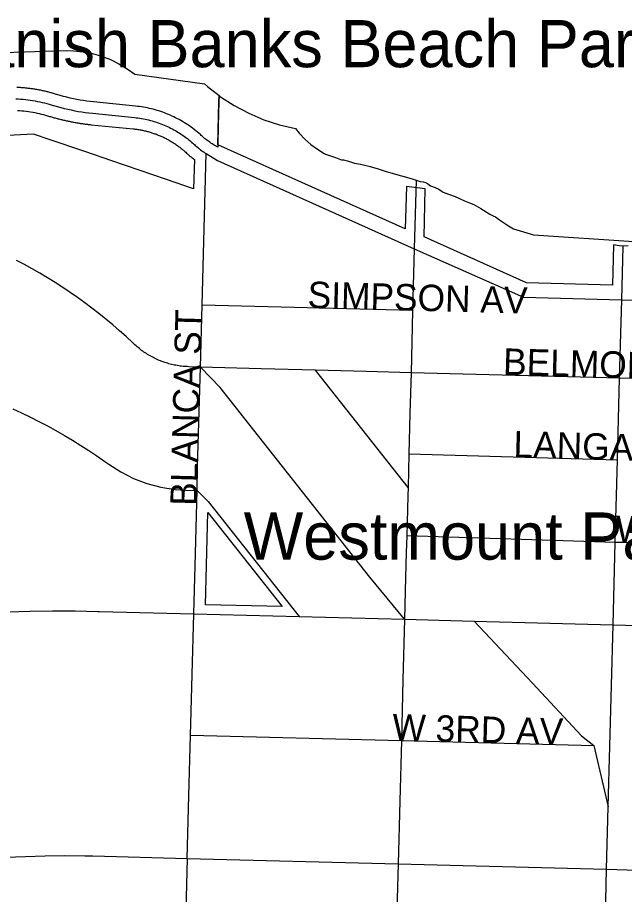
# Model space of a CAD drawing. Extents: x 482780 to 486928, y 5455974 to 5459836.
# Drawn here: x 484178 to 484821, y 5457356 to 5458285 of the extents above; entities that cross this region are included whole.
import ezdxf

# ---------------------------------------------------------------- set-up
doc = ezdxf.new("R2010")
doc.units = 0
for name, color, linetype in [('ParkLabels', 7, 'Continuous'), ('Parks', 7, 'Continuous'), ('StreetNames', 7, 'Continuous'), ('Streets', 7, 'Continuous')]:
    doc.layers.add(name, color=color, linetype=linetype)

msp = doc.modelspace()

# ---------------------------------------------------------------- linework, layer by layer
at = {"layer": 'Parks'}
for points in [[(484129.18, 5458247.37), (484229.39, 5458250.29), (484237.17, 5458250.08), (484247.16, 5458249.02), (484257.03, 5458247.1), (484266.69, 5458244.32), (484276.07, 5458240.71), (484285.1, 5458236.3), (484293.71, 5458231.12), (484301.84, 5458225.21), (484375.68, 5458215.19), (484379.16, 5458212.14), (484391.29, 5458202.66), (484391.11, 5458196.1), (484390.44, 5458170.7), (484389.91, 5458150.4), (484389.87, 5458147.97), (484388.64, 5458148.63), (484387.41, 5458149.32), (484386.21, 5458150.02), (484385.01, 5458150.74), (484383.83, 5458151.49), (484382.66, 5458152.25), (484381.5, 5458153.04), (484380.36, 5458153.85), (484379.23, 5458154.67), (484378.12, 5458155.52), (484377.02, 5458156.38), (484375.93, 5458157.26), (484374.86, 5458158.17), (484373.81, 5458159.09), (484373.25, 5458159.59), (484372.31, 5458160.44), (484371.5, 5458161.18), (484369.9, 5458162.58), (484368.28, 5458163.95), (484366.64, 5458165.29), (484364.97, 5458166.6), (484363.28, 5458167.89), (484361.57, 5458169.14), (484359.83, 5458170.37), (484358.08, 5458171.56), (484356.3, 5458172.72), (484354.5, 5458173.86), (484352.69, 5458174.96), (484350.85, 5458176.02), (484349, 5458177.06), (484347.13, 5458178.06), (484345.24, 5458179.04), (484343.34, 5458179.97), (484341.42, 5458180.88), (484339.48, 5458181.75), (484337.53, 5458182.59), (484335.56, 5458183.39), (484333.59, 5458184.16), (484331.59, 5458184.89), (484329.59, 5458185.59), (484327.57, 5458186.26), (484325.55, 5458186.88), (484323.51, 5458187.48), (484321.46, 5458188.04), (484319.4, 5458188.56), (484317.33, 5458189.04), (484315.26, 5458189.49), (484313.17, 5458189.91), (484311.09, 5458190.28), (484308.99, 5458190.62), (484306.89, 5458190.93), (484304.78, 5458191.19), (484302.67, 5458191.42), (484258.2, 5458195.89), (484254.62, 5458196.28), (484251.05, 5458196.74), (484247.49, 5458197.27), (484243.94, 5458197.85), (484240.4, 5458198.5), (484236.87, 5458199.21), (484233.36, 5458199.97), (484229.86, 5458200.81), (484226.37, 5458201.7), (484222.9, 5458202.65), (484219.44, 5458203.66), (484218.75, 5458203.87), (484216.71, 5458204.49), (484215.74, 5458204.78), (484214.77, 5458205.07), (484213.8, 5458205.34), (484212.83, 5458205.62), (484211.85, 5458205.88), (484210.88, 5458206.14), (484209.9, 5458206.4), (484208.92, 5458206.64), (484207.94, 5458206.89), (484206.95, 5458207.12), (484205.97, 5458207.35), (484204.98, 5458207.57), (484203.99, 5458207.79), (484203.01, 5458208), (484202.02, 5458208.2), (484201.02, 5458208.4), (484200.03, 5458208.59), (484199.04, 5458208.77), (484198.04, 5458208.95), (484197.05, 5458209.12), (484196.05, 5458209.29), (484195.05, 5458209.45), (484194.05, 5458209.6), (484193.05, 5458209.75), (484192.05, 5458209.89), (484191.05, 5458210.02), (484190.05, 5458210.15), (484189.04, 5458210.27), (484188.04, 5458210.38), (484187.04, 5458210.49), (484186.03, 5458210.59), (484185.02, 5458210.69), (484184.02, 5458210.78), (484183.01, 5458210.86), (484182, 5458210.94), (484180.99, 5458211.01), (484179.98, 5458211.07), (484179.97, 5458211.07), (484178.97, 5458211.13), (484177.97, 5458211.18), (484176.96, 5458211.22)], [(484824.88, 5458043.24), (484819.72, 5458042.76), (484815.42, 5458043.24), (484809.47, 5458044.25), (484808.32, 5458001.61), (484717.07, 5458004.05), (484608.51, 5458052.7), (484609.84, 5458103.83), (484589.8, 5458106.23), (484588.61, 5458061.2), (484389.91, 5458150.4), (484391.11, 5458196.1), (484391.29, 5458202.66), (484392.85, 5458201.44), (484407.42, 5458191.96), (484422.77, 5458183.78), (484438.77, 5458176.98), (484455.29, 5458171.59), (484472.23, 5458167.67), (484476.33, 5458162.62), (484482.19, 5458156.45), (484488.57, 5458150.8), (484495.42, 5458145.73), (484502.68, 5458141.27), (484504.24, 5458140.54), (484514.71, 5458136.8), (484518.07, 5458135.5), (484519.86, 5458134.85), (484521.01, 5458134.64), (484523.01, 5458134.4), (484528.31, 5458132.97), (484534.86, 5458131.1), (484541.18, 5458129.87), (484545.61, 5458128.95), (484551.31, 5458127.41), (484559.81, 5458124.9), (484568.36, 5458122.19), (484574.71, 5458120.2), (484580.81, 5458118.52), (484590.06, 5458116.05), (484596.89, 5458113.94), (484604.26, 5458111.65), (484607.48, 5458111.07), (484610.01, 5458110.55), (484612.24, 5458109.26), (484615.51, 5458107.05), (484620.24, 5458105.06), (484624.16, 5458103.35), (484626.66, 5458101.73), (484628.91, 5458100.3), (484634.32, 5458098.22), (484641.46, 5458095.7), (484646.73, 5458093.16), (484651.36, 5458090.95), (484656.65, 5458088.92), (484661.31, 5458087.1), (484668.56, 5458082.88), (484678.41, 5458076.8), (484681.79, 5458075.1), (484684.11, 5458073.9), (484688.6, 5458070.99), (484697.92, 5458064.4), (484699.62, 5458063.37), (484703.15, 5458061.47), (484724.68, 5458054.79), (484831.03, 5458048.04)], [(484177.54, 5458186.83), (484179.87, 5458186.69), (484182.19, 5458186.51), (484184.51, 5458186.29), (484186.83, 5458186.02), (484189.14, 5458185.72), (484191.44, 5458185.38), (484193.74, 5458184.99), (484196.03, 5458184.57), (484198.32, 5458184.11), (484200.6, 5458183.6), (484202.86, 5458183.06), (484205.12, 5458182.48), (484207.37, 5458181.86), (484209.6, 5458181.2), (484211.66, 5458180.59), (484212.64, 5458180.29), (484213.62, 5458180), (484214.6, 5458179.72), (484215.59, 5458179.43), (484216.57, 5458179.15), (484217.56, 5458178.88), (484218.55, 5458178.61), (484219.54, 5458178.35), (484220.53, 5458178.08), (484221.52, 5458177.83), (484222.51, 5458177.58), (484223.5, 5458177.33), (484224.5, 5458177.09), (484225.49, 5458176.85), (484226.49, 5458176.61), (484227.49, 5458176.38), (484228.49, 5458176.16), (484229.49, 5458175.93), (484230.49, 5458175.72), (484231.49, 5458175.5), (484232.49, 5458175.3), (484233.49, 5458175.09), (484234.5, 5458174.89), (484235.5, 5458174.7), (484236.51, 5458174.51), (484237.52, 5458174.32), (484238.52, 5458174.14), (484239.53, 5458173.96), (484240.54, 5458173.79), (484241.55, 5458173.62), (484242.56, 5458173.46), (484243.57, 5458173.3), (484244.59, 5458173.15), (484245.6, 5458173), (484246.61, 5458172.85), (484247.63, 5458172.71), (484248.64, 5458172.57), (484249.66, 5458172.44), (484250.67, 5458172.31), (484251.69, 5458172.19), (484252.71, 5458172.07), (484253.72, 5458171.96), (484254.74, 5458171.85), (484255.76, 5458171.74), (484300.26, 5458167.3), (484301.27, 5458167.19), (484302.28, 5458167.08), (484303.29, 5458166.95), (484304.29, 5458166.81), (484305.3, 5458166.66), (484306.3, 5458166.5), (484307.3, 5458166.33), (484308.3, 5458166.15), (484309.3, 5458165.96), (484310.29, 5458165.76), (484311.29, 5458165.55), (484312.28, 5458165.33), (484313.27, 5458165.1), (484314.25, 5458164.85), (484315.24, 5458164.6), (484316.22, 5458164.34), (484317.2, 5458164.07), (484318.17, 5458163.78), (484319.14, 5458163.49), (484320.11, 5458163.19), (484321.08, 5458162.87), (484322.04, 5458162.55), (484323, 5458162.21), (484323.95, 5458161.87), (484324.91, 5458161.52), (484325.86, 5458161.15), (484326.8, 5458160.78), (484327.74, 5458160.4), (484328.68, 5458160), (484329.61, 5458159.6), (484330.54, 5458159.19), (484331.46, 5458158.76), (484332.38, 5458158.33), (484333.29, 5458157.89), (484334.2, 5458157.44), (484335.11, 5458156.98), (484336.01, 5458156.51), (484336.9, 5458156.03), (484337.79, 5458155.54), (484338.68, 5458155.04), (484339.56, 5458154.54), (484340.43, 5458154.02), (484341.3, 5458153.49), (484342.17, 5458152.96), (484343.02, 5458152.42), (484343.88, 5458151.86), (484344.72, 5458151.3), (484345.56, 5458150.73), (484346.4, 5458150.15), (484347.23, 5458149.57), (484348.05, 5458148.97), (484348.86, 5458148.37), (484349.67, 5458147.75), (484350.48, 5458147.13), (484351.27, 5458146.5), (484352.06, 5458145.86), (484352.85, 5458145.22), (484353.62, 5458144.56), (484354.39, 5458143.9), (484355.15, 5458143.23), (484355.94, 5458142.52), (484356.86, 5458141.65), (484357.65, 5458140.94), (484358.45, 5458140.23), (484359.26, 5458139.53), (484360.07, 5458138.84), (484360.89, 5458138.16), (484361.72, 5458137.49), (484362.56, 5458136.83), (484363.4, 5458136.18), (484364.25, 5458135.53), (484365.11, 5458134.9), (484364.27, 5458103.65), (484335.42, 5458113.51), (484306.62, 5458123.37), (484277.76, 5458133.25), (484248.92, 5458143.13), (484211.31, 5458156), (484194.62, 5458161.72), (484153.36, 5458159.56)]]:
    msp.add_lwpolyline(points, dxfattribs=at)
msp.add_lwpolyline([(484379.42, 5457760.39), (484458.02, 5457660.75), (484376.77, 5457662.8)], close=True, dxfattribs=at)
at = {"layer": 'Streets'}
for points in [[(484175.83, 5458199.1), (484178.39, 5458198.99), (484180.95, 5458198.83), (484183.5, 5458198.63), (484186.05, 5458198.39), (484188.6, 5458198.09), (484191.14, 5458197.76), (484193.67, 5458197.38), (484196.2, 5458196.96), (484198.72, 5458196.49), (484201.23, 5458195.98), (484203.73, 5458195.42), (484206.22, 5458194.82), (484208.7, 5458194.18), (484211.17, 5458193.5), (484213.24, 5458192.89), (484215.28, 5458192.25), (484216.17, 5458191.98), (484219.81, 5458190.92), (484223.48, 5458189.92), (484227.15, 5458188.99), (484230.85, 5458188.12), (484234.56, 5458187.31), (484238.28, 5458186.57), (484242.02, 5458185.89), (484245.76, 5458185.28), (484249.52, 5458184.74), (484253.29, 5458184.26), (484257.06, 5458183.84), (484301.54, 5458179.38), (484303.45, 5458179.17), (484305.35, 5458178.92), (484307.24, 5458178.65), (484309.13, 5458178.34), (484311.02, 5458178), (484312.9, 5458177.62), (484314.77, 5458177.22), (484316.63, 5458176.78), (484318.49, 5458176.3), (484320.34, 5458175.8), (484322.18, 5458175.26), (484324.01, 5458174.69), (484325.82, 5458174.09), (484327.63, 5458173.46), (484329.43, 5458172.8), (484331.21, 5458172.1), (484332.99, 5458171.38), (484334.75, 5458170.62), (484336.49, 5458169.83), (484338.22, 5458169.01), (484339.94, 5458168.16), (484341.64, 5458167.29), (484343.33, 5458166.38), (484345, 5458165.44), (484346.66, 5458164.48), (484348.29, 5458163.48), (484349.91, 5458162.46), (484351.51, 5458161.41), (484353.1, 5458160.33), (484354.66, 5458159.22), (484356.2, 5458158.09), (484357.73, 5458156.93), (484359.23, 5458155.74), (484360.72, 5458154.53), (484362.18, 5458153.29), (484363.62, 5458152.03), (484364.2, 5458151.5), (484365.12, 5458150.63), (484366.01, 5458149.83), (484367.12, 5458148.84), (484368.25, 5458147.87), (484369.41, 5458146.92), (484370.58, 5458145.99), (484371.76, 5458145.08), (484372.97, 5458144.18), (484374.18, 5458143.32), (484375.41, 5458142.47), (484376.66, 5458141.64), (484377.54, 5458141.08), (484389.55, 5458133.92), (484389.55, 5458133.89), (484598.19, 5458040.26), (484713.92, 5457988.97), (484818.03, 5457986.12), (484830.14, 5457985.8)], [(484357.5, 5457393.72), (484359.27, 5457460.23), (484360.98, 5457524.53), (484361.31, 5457536.89), (484362.71, 5457588.83), (484364.4, 5457653.1), (484366.12, 5457716.99), (484367.91, 5457783.97), (484368.58, 5457808.83), (484371.45, 5457914.78), (484373.25, 5457980.54), (484374.67, 5458034.78), (484377.54, 5458141.08)], [(484600.1, 5458112.99), (484598.19, 5458040.26), (484596.45, 5457974.57), (484594.72, 5457908.78), (484593.59, 5457865.54), (484592.53, 5457822.31), (484591.59, 5457787.21), (484591.31, 5457778.29), (484590.21, 5457735.74), (484589.74, 5457718.27), (484589.03, 5457691.49), (484587.88, 5457647.46), (484586.17, 5457583.13), (484584.5, 5457518.71), (484582.81, 5457454.38), (484581.07, 5457387.91), (484579.75, 5457338.43)], [(484800.71, 5457332.61), (484802.02, 5457382.22), (484803.79, 5457448.65), (484808.97, 5457641.49), (484811.18, 5457728.59), (484813.46, 5457815.88), (484814.66, 5457859.45), (484815.82, 5457902.94), (484818.03, 5457986.12), (484819.55, 5458042.8)], [(485036.92, 5457897.06), (484815.82, 5457902.94), (484594.72, 5457908.78), (484547.04, 5457910.06), (484493.48, 5457911.5), (484435.94, 5457913.05), (484371.45, 5457914.78), (484359.27, 5457915.12), (484357.73, 5457915.18), (484356.19, 5457915.26), (484354.66, 5457915.37), (484353.13, 5457915.51), (484351.6, 5457915.67), (484350.07, 5457915.86), (484348.55, 5457916.08), (484347.03, 5457916.33), (484345.52, 5457916.6), (484344.01, 5457916.89), (484342.51, 5457917.22), (484341.01, 5457917.57), (484339.52, 5457917.94), (484338.04, 5457918.34), (484336.56, 5457918.77), (484335.09, 5457919.22), (484333.63, 5457919.7), (484332.18, 5457920.21), (484330.73, 5457920.74), (484329.3, 5457921.29), (484327.87, 5457921.87), (484326.46, 5457922.47), (484325.06, 5457923.1), (484323.66, 5457923.76), (484322.28, 5457924.43), (484320.91, 5457925.13), (484319.56, 5457925.86), (484318.22, 5457926.61), (484316.89, 5457927.38), (484315.57, 5457928.17), (484314.27, 5457928.99), (484312.98, 5457929.83), (484311.71, 5457930.7), (484310.45, 5457931.58), (484309.21, 5457932.49), (484307.98, 5457933.42), (484306.77, 5457934.37), (484305.58, 5457935.34), (484304.4, 5457936.33), (484303.25, 5457937.34), (484302.11, 5457938.37), (484301.07, 5457939.34), (484299.77, 5457940.57), (484292.83, 5457947), (484285.77, 5457953.31), (484278.6, 5457959.5), (484271.32, 5457965.56), (484263.94, 5457971.49), (484256.46, 5457977.29), (484248.88, 5457982.97), (484241.2, 5457988.5), (484233.42, 5457993.91), (484225.55, 5457999.18), (484217.59, 5458004.3), (484209.54, 5458009.29), (484201.41, 5458014.14), (484193.19, 5458018.85), (484184.89, 5458023.41), (484176.52, 5458027.82)], [(484596.45, 5457974.57), (484373.25, 5457980.54)], [(484587.88, 5457647.46), (484551.07, 5457691.95), (484392.4, 5457892.94), (484371.45, 5457914.78)], [(484591.59, 5457787.21), (484493.48, 5457911.5)], [(484172.75, 5457870.39), (484182.04, 5457866.11), (484191.26, 5457861.67), (484200.39, 5457857.06), (484209.45, 5457852.3), (484218.42, 5457847.38), (484227.3, 5457842.31), (484236.09, 5457837.08), (484244.79, 5457831.7), (484253.4, 5457826.17), (484261.9, 5457820.49), (484270.31, 5457814.66), (484274.34, 5457811.79), (484287.03, 5457803.58), (484300.62, 5457796.66), (484314.86, 5457791.19), (484329.6, 5457787.24), (484344.67, 5457784.85), (484355.74, 5457784.27), (484355.74, 5457784.27), (484367.91, 5457783.97), (484379.82, 5457772.29), (484476.08, 5457650.28)], [(484813.46, 5457815.88), (484592.53, 5457822.31)], [(485032.31, 5457722.91), (484821.19, 5457728.63), (484811.18, 5457728.59), (484590.21, 5457735.74)], [(483813.72, 5457599.7), (483930.19, 5457625.05), (483953.6, 5457629.93), (483977.08, 5457634.4), (484000.64, 5457638.46), (484024.27, 5457642.11), (484047.96, 5457645.35), (484071.7, 5457648.17), (484095.48, 5457650.57), (484119.3, 5457652.56), (484143.16, 5457654.14), (484167.04, 5457655.3), (484190.93, 5457656.04), (484214.84, 5457656.37), (484238.75, 5457656.27), (484262.65, 5457655.76), (484264.42, 5457655.71), (484364.4, 5457653.1), (484476.08, 5457650.28), (484587.88, 5457647.46), (484661.8, 5457645.45), (484808.97, 5457641.49), (485030.02, 5457635.55), (485251.12, 5457629.52)], [(484661.8, 5457645.45), (484706.49, 5457597.61), (484723.43, 5457579.47), (484775.47, 5457523.76), (484788.45, 5457513.35), (484803.79, 5457448.65)], [(484360.98, 5457524.53), (484584.5, 5457518.71), (484788.45, 5457513.35)], [(484165.1, 5457395.05), (484186.03, 5457395.98), (484206.97, 5457396.54), (484227.91, 5457396.74), (484248.86, 5457396.57), (484257.49, 5457396.4), (484357.5, 5457393.72), (484581.07, 5457387.91), (484802.02, 5457382.22), (484867.32, 5457380.43), (484890.11, 5457379.8), (484910.5, 5457379.28), (485023.18, 5457376.21), (485033.05, 5457369.22), (485156.24, 5457324.57)], [(484357.5, 5457393.72), (484354.95, 5457296.83), (484353.68, 5457249.49), (484352.41, 5457202.15), (484351.11, 5457152.68), (484349.89, 5457107.27), (484348.64, 5457061.71), (484347.35, 5457013.4), (484346.1, 5456964.28), (484344.83, 5456916.22), (484343.58, 5456868.13), (484342.23, 5456817.94), (484340.85, 5456765.59), (484339.5, 5456715.34), (484338.17, 5456665.09), (484336.85, 5456614.84), (484335.52, 5456564.59), (484334.18, 5456514.34), (484332.84, 5456464.04), (484331.5, 5456413.79), (484330.17, 5456363.48), (484328.84, 5456313.14), (484327.51, 5456262.84), (484325.9, 5456202.49)]]:
    msp.add_lwpolyline(points, dxfattribs=at)

# ---------------------------------------------------------------- texts
at = {"layer": 'ParkLabels'}
for s, p in [('Spanish Banks Beach Park', (484055.22, 5458232.68)), ('Westmount Park', (484417.39, 5457710.57))]:
    msp.add_text(s, height=50, dxfattribs=at).set_placement(p)
at = {"layer": 'StreetNames'}
for s, rotation, p in [('SIMPSON AV', 358.46773, (484484.85, 5457977.55)), ('BLANCA ST', 88.464, (484367.52, 5457767.4)), ('BELMONT AV', 358.40012, (484691.98, 5457906.69)), ('LANGARA AV', 358.33122, (484702.99, 5457819.1)), ('W 1ST AV', 358.3375, (484811.26, 5457729.33)), ('W 3RD AV', 358.50203, (484574.71, 5457518.94))]:
    msp.add_text(s, height=28, rotation=rotation, dxfattribs=at).set_placement(p)

doc.saveas('drawing.dxf')
